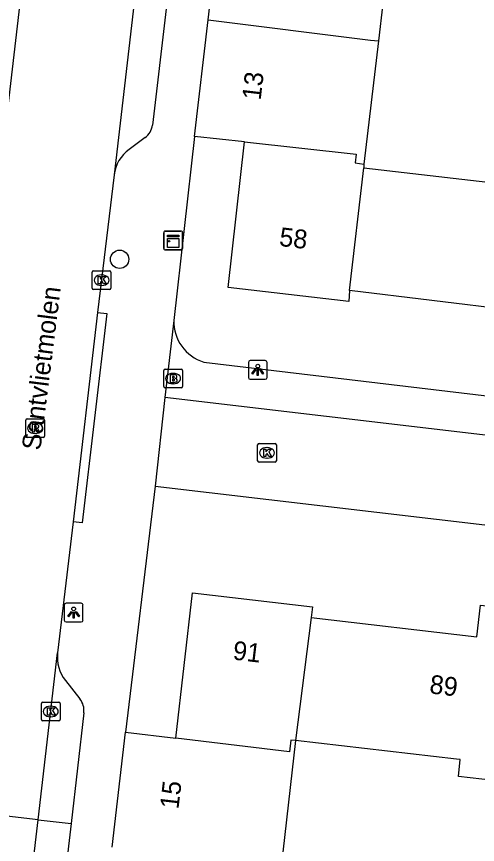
# Model space of a CAD drawing. Extents: x 161243 to 161752, y 384138 to 384885.
# Drawn here: x 161456.96 to 161481.56, y 384547.67 to 384591.8 of the extents above; entities that cross this region are included whole.
import ezdxf

# ---------------------------------------------------------------- set-up
doc = ezdxf.new("R2010")
doc.units = 0
for name, color, linetype in [('IMGEO_Boom', 7, 'Continuous'), ('IMGEO_Brandkraan', 7, 'Continuous'), ('IMGEO_Kast', 7, 'Continuous'), ('IMGEO_Kolk', 7, 'Continuous'), ('IMGEO_Lichtpunt', 7, 'Continuous'), ('IMGEO_Openbare_ruimte_label', 7, 'Continuous'), ('IMGEO_Pand', 7, 'Continuous'), ('IMGEO_Pand_nummerreeks', 7, 'Continuous'), ('IMGEO_Parkeervlak_open', 7, 'Continuous'), ('IMGEO_Rijbaan_lokaal_open', 7, 'Continuous'), ('IMGEO_Rioolput', 7, 'Continuous'), ('IMGEO_Voetpad_open', 7, 'Continuous')]:
    doc.layers.add(name, color=color, linetype=linetype)

msp = doc.modelspace()

# ---------------------------------------------------------------- linework, layer by layer
at = {"layer": 'IMGEO_Boom'}
msp.add_circle((161462.46, 384578.862), 0.489, dxfattribs=at)
at = {"layer": 'IMGEO_Brandkraan'}
for p, q in [((161464.815, 384572.077), (161464.815, 384572.929)), ((161464.89, 384573.003), (161465.742, 384573.003)), ((161465.303, 384572.783), (161465.328, 384572.783)), ((161465.816, 384572.929), (161465.816, 384572.077)), ((161465.742, 384572.003), (161464.89, 384572.003)), ((161465.326, 384572.223), (161465.301, 384572.223))]:
    msp.add_line(p, q, dxfattribs=at)
for points in [[(161464.815, 384572.077), (161464.815, 384572.929)], [(161464.89, 384573.003), (161465.742, 384573.003)], [(161465.816, 384572.929), (161465.816, 384572.077)], [(161465.163, 384572.703), (161465.163, 384572.303), (161465.376, 384572.303)], [(161465.394, 384572.703), (161465.163, 384572.703)], [(161465.342, 384572.622), (161465.288, 384572.622), (161465.288, 384572.546)], [(161465.288, 384572.546), (161465.341, 384572.546)], [(161465.35, 384572.47), (161465.288, 384572.47), (161465.288, 384572.389)], [(161465.288, 384572.389), (161465.35, 384572.389)], [(161465.742, 384572.003), (161464.89, 384572.003)]]:
    msp.add_lwpolyline(points, dxfattribs=at)
for centre, radius, start, end in [((161464.892, 384572.927), 0.0765, 91.552, 178.448), ((161464.892, 384572.927), 0.0765, 91.552, 178.448), ((161465.74, 384572.927), 0.0765, 1.552, 88.448), ((161465.74, 384572.927), 0.0765, 1.552, 88.448), ((161465.343, 384572.584), 0.0379, 267.8285, 90.9355), ((161465.351, 384572.429), 0.0404, 269.8759, 90.5077), ((161465.382, 384572.554), 0.251, 268.6676, 293.5347), ((161465.398, 384572.558), 0.145, 59.4692, 91.5367), ((161465.423, 384572.605), 0.0922, 285.5137, 58.1501), ((161465.428, 384572.413), 0.105, 301.3115, 78.989), ((161464.892, 384572.079), 0.0765, 181.552, 268.448), ((161464.892, 384572.079), 0.0765, 181.552, 268.448), ((161465.74, 384572.079), 0.0765, 271.552, 358.448), ((161465.74, 384572.079), 0.0765, 271.552, 358.448)]:
    msp.add_arc(centre, radius, start, end, dxfattribs=at)
for centre, major_axis, ratio, start_param, end_param in [((161465.302, 384572.503), (-0.387, 0.002), 0.722429, 4.712389, 7.853982), ((161465.327, 384572.503), (-0.39, 0.002), 0.717154, 1.570796, 4.712389)]:
    msp.add_ellipse(centre, major_axis=major_axis, ratio=ratio, start_param=start_param, end_param=end_param, dxfattribs=at)
at = {"layer": 'IMGEO_Kast'}
for p, q in [((161464.82, 384579.437), (161464.82, 384580.278)), ((161464.82, 384580.278), (161464.82, 384579.437)), ((161464.895, 384580.362), (161465.736, 384580.362)), ((161465.736, 384580.362), (161464.895, 384580.362)), ((161465.82, 384580.287), (161465.82, 384579.446)), ((161465.82, 384579.446), (161465.82, 384580.287)), ((161465.745, 384579.362), (161464.904, 384579.362)), ((161464.904, 384579.362), (161465.745, 384579.362))]:
    msp.add_line(p, q, dxfattribs=at)
for points in [[(161465.015, 384580.152), (161465.615, 384580.152), (161465.615, 384580.067), (161465.015, 384580.067), (161465.015, 384580.152)], [(161465.015, 384579.977), (161465.615, 384579.977), (161465.615, 384579.488), (161465.015, 384579.488), (161465.015, 384579.977)]]:
    msp.add_lwpolyline(points, dxfattribs=at)
msp.add_circle((161465.099, 384579.826), 0.0377, dxfattribs=at)
for centre, start, end in [((161464.898, 384580.284), 92.4484, 184.2845), ((161464.898, 384580.284), 92.4484, 184.2845), ((161465.742, 384580.284), 2.4484, 94.2845), ((161465.742, 384580.284), 2.4484, 94.2845), ((161464.898, 384579.44), 182.4484, 274.2845), ((161464.898, 384579.44), 182.4484, 274.2845), ((161465.742, 384579.44), 272.4484, 4.2845), ((161465.742, 384579.44), 272.4484, 4.2845)]:
    msp.add_arc(centre, 0.0779, start, end, dxfattribs=at)
at = {"layer": 'IMGEO_Kolk'}
for p, q in [((161460.998, 384577.322), (161460.998, 384578.174)), ((161461.073, 384578.248), (161461.925, 384578.248)), ((161461.999, 384578.174), (161461.999, 384577.322)), ((161461.486, 384578.028), (161461.511, 384578.028)), ((161461.925, 384577.248), (161461.073, 384577.248)), ((161461.509, 384577.468), (161461.484, 384577.468)), ((161469.828, 384568.117), (161469.828, 384568.969)), ((161469.903, 384569.043), (161470.755, 384569.043)), ((161470.316, 384568.823), (161470.341, 384568.823)), ((161470.829, 384568.969), (161470.829, 384568.117)), ((161470.755, 384568.043), (161469.903, 384568.043)), ((161470.339, 384568.263), (161470.314, 384568.263)), ((161458.285, 384554.33), (161458.285, 384555.182)), ((161458.36, 384555.256), (161459.212, 384555.256)), ((161459.286, 384555.182), (161459.286, 384554.33)), ((161458.773, 384555.036), (161458.798, 384555.036)), ((161459.212, 384554.256), (161458.36, 384554.256)), ((161458.796, 384554.476), (161458.771, 384554.476))]:
    msp.add_line(p, q, dxfattribs=at)
for points in [[(161460.998, 384577.322), (161460.998, 384578.174)], [(161461.073, 384578.248), (161461.925, 384578.248)], [(161461.999, 384578.174), (161461.999, 384577.322)], [(161461.319, 384577.948), (161461.442, 384577.948), (161461.442, 384577.797), (161461.572, 384577.948), (161461.736, 384577.948), (161461.59, 384577.797), (161461.743, 384577.548), (161461.591, 384577.548), (161461.506, 384577.712), (161461.442, 384577.645), (161461.442, 384577.548), (161461.319, 384577.548), (161461.319, 384577.948)], [(161461.925, 384577.248), (161461.073, 384577.248)], [(161469.828, 384568.117), (161469.828, 384568.969)], [(161469.903, 384569.043), (161470.755, 384569.043)], [(161470.829, 384568.969), (161470.829, 384568.117)], [(161470.149, 384568.743), (161470.272, 384568.743), (161470.272, 384568.592), (161470.402, 384568.743), (161470.566, 384568.743), (161470.42, 384568.592), (161470.573, 384568.343), (161470.421, 384568.343), (161470.336, 384568.507), (161470.272, 384568.44), (161470.272, 384568.343), (161470.149, 384568.343), (161470.149, 384568.743)], [(161470.755, 384568.043), (161469.903, 384568.043)], [(161458.285, 384554.33), (161458.285, 384555.182)], [(161458.36, 384555.256), (161459.212, 384555.256)], [(161459.286, 384555.182), (161459.286, 384554.33)], [(161458.606, 384554.956), (161458.729, 384554.956), (161458.729, 384554.805), (161458.859, 384554.956), (161459.023, 384554.956), (161458.877, 384554.805), (161459.03, 384554.556), (161458.878, 384554.556), (161458.793, 384554.72), (161458.729, 384554.653), (161458.729, 384554.556), (161458.606, 384554.556), (161458.606, 384554.956)], [(161459.212, 384554.256), (161458.36, 384554.256)]]:
    msp.add_lwpolyline(points, dxfattribs=at)
for centre, start, end in [((161461.075, 384578.172), 91.552, 178.448), ((161461.075, 384578.172), 91.552, 178.448), ((161461.923, 384578.172), 1.552, 88.448), ((161461.923, 384578.172), 1.552, 88.448), ((161461.075, 384577.324), 181.552, 268.448), ((161461.075, 384577.324), 181.552, 268.448), ((161461.923, 384577.324), 271.552, 358.448), ((161461.923, 384577.324), 271.552, 358.448), ((161469.905, 384568.967), 91.552, 178.448), ((161469.905, 384568.967), 91.552, 178.448), ((161470.753, 384568.967), 1.552, 88.448), ((161470.753, 384568.967), 1.552, 88.448), ((161469.905, 384568.119), 181.552, 268.448), ((161469.905, 384568.119), 181.552, 268.448), ((161470.753, 384568.119), 271.552, 358.448), ((161470.753, 384568.119), 271.552, 358.448), ((161458.362, 384555.18), 91.552, 178.448), ((161458.362, 384555.18), 91.552, 178.448), ((161459.21, 384555.18), 1.552, 88.448), ((161459.21, 384555.18), 1.552, 88.448), ((161458.362, 384554.332), 181.552, 268.448), ((161458.362, 384554.332), 181.552, 268.448), ((161459.21, 384554.332), 271.552, 358.448), ((161459.21, 384554.332), 271.552, 358.448)]:
    msp.add_arc(centre, 0.0765, start, end, dxfattribs=at)
for centre, major_axis, ratio, start_param, end_param in [((161461.485, 384577.748), (-0.387, 0.002), 0.722429, 4.712389, 7.853982), ((161461.51, 384577.748), (-0.39, 0.002), 0.717154, 1.570796, 4.712389), ((161470.315, 384568.543), (-0.387, 0.002), 0.722429, 4.712389, 7.853982), ((161470.34, 384568.543), (-0.39, 0.002), 0.717154, 1.570796, 4.712389), ((161458.772, 384554.756), (-0.387, 0.002), 0.722429, 4.712389, 7.853982), ((161458.797, 384554.756), (-0.39, 0.002), 0.717154, 1.570796, 4.712389)]:
    msp.add_ellipse(centre, major_axis=major_axis, ratio=ratio, start_param=start_param, end_param=end_param, dxfattribs=at)
at = {"layer": 'IMGEO_Lichtpunt'}
for p, q in [((161469.333, 384573.369), (161469.333, 384572.562)), ((161469.333, 384573.369), (161469.333, 384572.562)), ((161470.235, 384573.464), (161469.427, 384573.464)), ((161470.235, 384573.464), (161469.427, 384573.464)), ((161470.329, 384572.562), (161470.329, 384573.369)), ((161470.329, 384572.562), (161470.329, 384573.369)), ((161469.427, 384572.468), (161470.235, 384572.468)), ((161469.427, 384572.468), (161470.235, 384572.468)), ((161459.509, 384560.429), (161459.509, 384559.622)), ((161459.509, 384560.429), (161459.509, 384559.622)), ((161460.411, 384560.524), (161459.603, 384560.524)), ((161460.411, 384560.524), (161459.603, 384560.524)), ((161460.505, 384559.622), (161460.505, 384560.429)), ((161460.505, 384559.622), (161460.505, 384560.429)), ((161459.603, 384559.528), (161460.411, 384559.528)), ((161459.603, 384559.528), (161460.411, 384559.528))]:
    msp.add_line(p, q, dxfattribs=at)
for points in [[(161469.707, 384573.033), (161469.746, 384573.005), (161469.558, 384572.743), (161469.52, 384572.77), (161469.707, 384573.033)], [(161469.809, 384572.985), (161469.856, 384572.985), (161469.856, 384572.663), (161469.809, 384572.663), (161469.809, 384572.985)], [(161469.919, 384573.005), (161469.957, 384573.032), (161470.144, 384572.77), (161470.105, 384572.742), (161469.919, 384573.005)], [(161459.883, 384560.093), (161459.922, 384560.065), (161459.734, 384559.803), (161459.696, 384559.83), (161459.883, 384560.093)], [(161459.985, 384560.045), (161460.032, 384560.045), (161460.032, 384559.723), (161459.985, 384559.723), (161459.985, 384560.045)], [(161460.095, 384560.065), (161460.133, 384560.092), (161460.32, 384559.83), (161460.281, 384559.802), (161460.095, 384560.065)]]:
    msp.add_lwpolyline(points, dxfattribs=at)
for centre in [(161469.832, 384573.167), (161460.008, 384560.227)]:
    msp.add_circle(centre, 0.0994, dxfattribs=at)
for centre, start, end in [((161469.427, 384573.369), 90, 180), ((161469.427, 384573.369), 90, 180), ((161470.235, 384573.369), 0, 90), ((161470.235, 384573.369), 0, 90), ((161469.427, 384572.562), 180, 270), ((161469.427, 384572.562), 180, 270), ((161470.235, 384572.562), 270, 0), ((161470.235, 384572.562), 270, 360), ((161459.603, 384560.429), 90, 180), ((161459.603, 384560.429), 90, 180), ((161460.411, 384560.429), 0, 90), ((161460.411, 384560.429), 0, 90), ((161459.603, 384559.622), 180, 270), ((161459.603, 384559.622), 180, 270), ((161460.411, 384559.622), 270, 0), ((161460.411, 384559.622), 270, 360)]:
    msp.add_arc(centre, 0.0946, start, end, dxfattribs=at)
at = {"layer": 'IMGEO_Pand'}
for points in [[(161467.179, 384591.626), (161467.872, 384597.633)], [(161476.974, 384596.505), (161476.271, 384590.5)], [(161466.461, 384585.408), (161467.179, 384591.626)], [(161467.179, 384591.626), (161475.852, 384590.552), (161476.271, 384590.5)], [(161476.271, 384590.5), (161475.503, 384583.942)], [(161469.124, 384585.125), (161466.461, 384585.408)], [(161474.735, 384577.196), (161474.694, 384576.61), (161468.258, 384577.355), (161469.124, 384585.125)], [(161469.124, 384585.125), (161475.091, 384584.461), (161475.04, 384584), (161475.503, 384583.942)], [(161475.503, 384583.942), (161475.502, 384583.743)], [(161474.735, 384577.196), (161475.502, 384583.743)], [(161475.502, 384583.743), (161484.26, 384582.718), (161484.364, 384583.611), (161490.562, 384582.885)], [(161489.48, 384573.718), (161483.32, 384574.444), (161483.517, 384576.132), (161474.735, 384577.196)], [(161465.466, 384553.329), (161466.359, 384561.082), (161472.764, 384560.327), (161472.692, 384559.759)], [(161472.692, 384559.759), (161481.523, 384558.733), (161481.721, 384560.427), (161487.838, 384559.733)], [(161472.692, 384559.759), (161471.853, 384553.203)], [(161462.056, 384547.515), (161462.781, 384553.656)], [(161462.781, 384553.656), (161465.466, 384553.329)], [(161471.853, 384553.203), (161471.597, 384553.232), (161471.52, 384552.597), (161465.466, 384553.329)], [(161471.853, 384553.203), (161471.079, 384546.471)], [(161486.778, 384550.579), (161480.542, 384551.296), (161480.645, 384552.191), (161480.438, 384552.215), (161471.853, 384553.203)]]:
    msp.add_lwpolyline(points, dxfattribs=at)
at = {"layer": 'IMGEO_Parkeervlak_open'}
msp.add_lwpolyline([(161458.115, 384548.986), (161459.867, 384548.782)], dxfattribs=at)
at = {"layer": 'IMGEO_Rijbaan_lokaal_open'}
for points in [[(161458.88, 384607.496), (161456.155, 384584.108)], [(161464.9, 384606.794), (161462.171, 384583.365)], [(161462.171, 384583.365), (161461.494, 384577.785), (161461.287, 384576.027)], [(161461.287, 384576.027), (161459.972, 384564.87)], [(161464.869, 384571.501), (161464.362, 384566.766)], [(161512.889, 384565.866), (161500, 384567.378), (161464.869, 384571.501)], [(161464.362, 384566.766), (161482.25, 384564.675)], [(161459.972, 384564.87), (161459.149, 384557.883)], [(161458.115, 384548.986), (161459.149, 384557.883)], [(161458.115, 384548.986), (161452.178, 384549.677)], [(161457.814, 384546.404), (161458.115, 384548.986)]]:
    msp.add_lwpolyline(points, dxfattribs=at)
at = {"layer": 'IMGEO_Rioolput'}
for p, q in [((161457.449, 384569.435), (161457.449, 384570.287)), ((161457.524, 384570.361), (161458.376, 384570.361)), ((161457.937, 384570.141), (161457.962, 384570.141)), ((161458.45, 384570.287), (161458.45, 384569.435)), ((161458.376, 384569.361), (161457.524, 384569.361)), ((161457.96, 384569.581), (161457.935, 384569.581))]:
    msp.add_line(p, q, dxfattribs=at)
for points in [[(161457.449, 384569.435), (161457.449, 384570.287)], [(161457.524, 384570.361), (161458.376, 384570.361)], [(161458.45, 384570.287), (161458.45, 384569.435)], [(161458.038, 384570.059), (161457.786, 384570.061), (161457.786, 384569.661)], [(161457.786, 384569.661), (161457.91, 384569.661), (161457.91, 384569.823), (161457.921, 384569.823)], [(161457.964, 384569.98), (161457.91, 384569.98), (161457.91, 384569.899)], [(161457.91, 384569.899), (161457.962, 384569.899)], [(161457.968, 384569.794), (161458.039, 384569.661), (161458.179, 384569.661), (161458.114, 384569.787)], [(161458.376, 384569.361), (161457.524, 384569.361)]]:
    msp.add_lwpolyline(points, dxfattribs=at)
for centre, radius, start, end in [((161457.526, 384570.285), 0.0765, 91.552, 178.448), ((161457.526, 384570.285), 0.0765, 91.552, 178.448), ((161458.374, 384570.285), 0.0765, 1.552, 88.448), ((161458.374, 384570.285), 0.0765, 1.552, 88.448), ((161457.92, 384569.77), 0.0533, 26.0293, 88.6989), ((161457.946, 384570.088), 0.19, 274.7715, 282.9687), ((161457.97, 384569.884), 0.0964, 77.0061, 93.1865), ((161457.984, 384569.941), 0.0378, 276.6634, 79.6772), ((161458.037, 384569.949), 0.109, 350.3612, 89.416), ((161458.035, 384569.949), 0.112, 277.5842, 350.9817), ((161458.019, 384569.734), 0.108, 29.5134, 73.7905), ((161457.526, 384569.437), 0.0765, 181.552, 268.448), ((161457.526, 384569.437), 0.0765, 181.552, 268.448), ((161458.374, 384569.437), 0.0765, 271.552, 358.448), ((161458.374, 384569.437), 0.0765, 271.552, 358.448)]:
    msp.add_arc(centre, radius, start, end, dxfattribs=at)
for centre, major_axis, ratio, start_param, end_param in [((161457.936, 384569.861), (-0.387, 0.002), 0.722429, 4.712389, 7.853982), ((161457.961, 384569.861), (-0.39, 0.002), 0.717154, 1.570796, 4.712389)]:
    msp.add_ellipse(centre, major_axis=major_axis, ratio=ratio, start_param=start_param, end_param=end_param, dxfattribs=at)
at = {"layer": 'IMGEO_Voetpad_open'}
for points in [[(161469.135, 384627.927), (161464.207, 384586.016)], [(161463.819, 384585.349), (161462.961, 384584.717)], [(161466.461, 384585.408), (161465.355, 384575.608)], [(161461.287, 384576.027), (161461.783, 384575.969), (161460.468, 384564.812), (161459.972, 384564.87)], [(161465.355, 384575.608), (161464.869, 384571.501)], [(161466.953, 384573.387), (161500, 384569.458), (161516.744, 384567.467)], [(161464.362, 384566.766), (161462.781, 384553.656)], [(161459.571, 384556.403), (161460.343, 384555.425)], [(161460.551, 384554.685), (161459.867, 384548.782)], [(161459.867, 384548.782), (161459.568, 384546.2)]]:
    msp.add_lwpolyline(points, dxfattribs=at)
for centre, radius, start, end in [((161463.252, 384586.125), 0.961, 306.1364, 353.4897), ((161464.127, 384583.129), 1.97, 126.2864, 173.1164), ((161467.617, 384575.55), 2.263, 178.5353, 252.9344), ((161461.161, 384557.657), 2.025, 173.5782, 218.2512), ((161459.56, 384554.806), 0.999, 353.0643, 38.3351)]:
    msp.add_arc(centre, radius, start, end, dxfattribs=at)

# ---------------------------------------------------------------- texts
at = {"layer": 'IMGEO_Openbare_ruimte_label'}
msp.add_text('Santvlietmolen', height=1, rotation=82.8181, dxfattribs=at).set_placement((161458.228, 384568.646))
at = {"layer": 'IMGEO_Pand_nummerreeks'}
for s, rotation, p in [('13', 83.3712, (161469.986, 384587.319)), ('58', 353.3971, (161470.947, 384579.58)), ('91', 353.2772, (161468.469, 384557.531)), ('89', 353.373, (161478.966, 384555.728)), ('15', 83.3027, (161465.599, 384549.524))]:
    msp.add_text(s, height=1, rotation=rotation, dxfattribs=at).set_placement(p)

doc.saveas('drawing.dxf')
